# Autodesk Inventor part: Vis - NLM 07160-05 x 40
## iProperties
Shininess: 64.0
Length Units: 11269
Angle Units: 11279
Time Units: 11290
Mass Units: 11283
Length Display Precision: 3
Angle Display Precision: 2
Compacted: True
Part Number: Vis - NLM 07160-05 x 40
Document SubType Name: Modeling
Created: 2005-02
Material: Par défaut
Designer: LEGERET Philippe
Catalog Web Link: www.traceparts.com
Description: Vis CHC acier M5 x 40 mm
Vendor: NORELEM
Density: 0.0
Volumn: 0.0
Area: 0.0
PropertySet Name: Model Information
Control State: 0
Master: False
Checked Out: False
REFERENCE: NLM 07160-05 x 40
MATERIAL: Acier
Author: Trace Parts S.A.
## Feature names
1. Base1
